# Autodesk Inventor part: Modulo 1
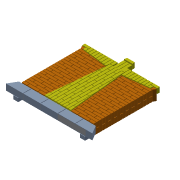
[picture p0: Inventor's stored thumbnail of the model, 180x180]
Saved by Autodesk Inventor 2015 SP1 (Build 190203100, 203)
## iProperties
Created: 2015-04
Part Number: Modulo 1
Material: Generic
Document SubType Name: Modeling
Designer: treina2
Density: 1 g/cm^3
Appearance: Default
Author: treina2
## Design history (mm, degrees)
sketch "Sketch1"
  geometry: L1 (1091.806, 200)-(1091.806, 440) reference; L2 (1091.806, 440)-(1033.806, 440) reference; L3 (1033.806, 440)-(1033.806, 200) reference; L4 (1033.806, 200)-(1091.806, 200) reference; L5 (1159.806, 200)-(1159.806, 315) reference; L6 (1159.806, 315)-(1101.806, 315) reference; L7 (1101.806, 315)-(1101.806, 200) reference; L8 (1101.806, 200)-(1159.806, 200) reference; L9 (1227.806, 200)-(1227.806, 440) reference; L10 (1227.806, 440)-(1169.806, 440) reference; L11 (1169.806, 440)-(1169.806, 200) reference; L12 (1169.806, 200)-(1227.806, 200) reference; L13 (1024, 200)-(1024, 315) reference; L14 (1024, 315)-(966, 315) reference; L15 (966, 315)-(966, 200) reference; L16 (966, 200)-(1024, 200) reference; L17 (1169.806, 1464.632)-(1169.806, 1450) reference; L18 (1169.806, 1450)-(1171.263, 1450) reference; L19 (1284.348, 315)-(1237.806, 315) reference; L20 (1237.806, 315)-(1237.806, 200) reference; L21 (1237.806, 200)-(1295.806, 200) reference; L22 (1259.439, 565)-(1283.351, 325) reference; L23 (1259.439, 565)-(1237.806, 565) reference; L24 (1237.806, 565)-(1237.806, 325) reference; L25 (1237.806, 325)-(1283.351, 325) reference; L26 (1169.806, 1565)-(1177.128, 1492) reference; L27 (1237.806, 1498.938)-(1295.806, 1505.57) reference; L28 (1295.806, 1505.57)-(1295.806, 1686) reference; L29 (1295.806, 1686)-(1237.806, 1686) reference; L30 (1237.806, 1686)-(1237.806, 1498.938) reference; L31 (1159.806, 325)-(1159.806, 565) reference; L32 (1159.806, 565)-(1101.806, 565) reference; L33 (1101.806, 565)-(1101.806, 325) reference; L34 (1101.806, 325)-(1159.806, 325) reference; L35 (1703.806, 1552.224)-(1703.806, 1686) reference; L36 (1703.806, 1686)-(1645.806, 1686) reference; L37 (1645.806, 1686)-(1645.806, 1545.592) reference; L38 (1024, 325)-(1024, 565) reference; L39 (1024, 565)-(966, 565) reference; L40 (966, 565)-(966, 325) reference; L41 (966, 325)-(1024, 325) reference; L42 (1091.806, 450)-(1091.806, 690) reference; L43 (1091.806, 690)-(1033.806, 690) reference; L44 (1033.806, 690)-(1033.806, 450) reference; L45 (1033.806, 450)-(1091.806, 450) reference; L46 (1227.806, 450)-(1227.806, 690) reference; L47 (1227.806, 690)-(1169.806, 690) reference; L48 (1169.806, 690)-(1169.806, 450) reference; L49 (1169.806, 450)-(1227.806, 450) reference; L50 (1159.806, 575)-(1159.806, 815) reference; L51 (1159.806, 815)-(1101.806, 815) reference; L52 (1101.806, 815)-(1101.806, 575) reference; L53 (1101.806, 575)-(1159.806, 575) reference; L54 (1237.806, 782.132)-(1237.806, 575) reference; L55 (1237.806, 575)-(1258.443, 575) reference; L56 (1024, 575)-(1024, 815) reference; L57 (1024, 815)-(966, 815) reference; L58 (966, 815)-(966, 575) reference; L59 (966, 575)-(1024, 575) reference; L60 (1091.806, 700)-(1091.806, 940) reference; L61 (1091.806, 940)-(1033.806, 940) reference; L62 (1033.806, 940)-(1033.806, 700) reference; L63 (1033.806, 700)-(1091.806, 700) reference; L64 (1227.806, 700)-(1227.806, 882.5) reference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; 1 further point
  constraints: 1754 end point, 397 horizontal, 367 vertical, 18 point on line, 953 other
workplane "Work Plane1"
sketch "Sketch2"
  geometry: L1 (1990, 0)-(1600, 0) reference; L2 (1990, 0)-(1880.303, 190) reference; L3 (1765, 190)-(1880.303, 190) reference; L4 (1600, 190)-(1880.303, 190) reference; L5 (1600, 0)-(1600, 190) reference; L6 (1590, 190)-(1590, 0) reference; L7 (1200, 190)-(1590, 190) reference; L8 (1590, 0)-(1200, 0) reference; L9 (1200, 0)-(1200, 190) reference; L10 (1190, 190)-(1190, 0) reference; L11 (1190, 0)-(800, 0) reference; L12 (800, 190)-(1190, 190) reference; L13 (800, 0)-(800, 190) reference; L14 (790, 190)-(790, 0) reference; L15 (400, 190)-(790, 190) reference; L16 (790, 0)-(400, 0) reference; L17 (400, 0)-(400, 190) reference; L18 (390, 190)-(390, 0) reference; L19 (109.697, 190)-(390, 190) reference; L20 (390, 0)-(0, 0) reference; L21 (0, 0)-(109.697, 190) reference; 1 further point
extrude "Extrusion1" new body sketch "Sketch2" distance "d2" = 140 (= BLOCO_PADRAO_LARG); taper "d3" = 0 deg
extrude "Extrusion2" new body sketch "Sketch2" distance "d4" = 140 (= BLOCO_PADRAO_LARG); taper "d5" = 0 deg
extrude "Extrusion3" new body sketch "Sketch2" distance "d6" = 140 (= BLOCO_PADRAO_LARG); taper "d7" = 0 deg
extrude "Extrusion4" new body sketch "Sketch2" distance "d8" = 140 (= BLOCO_PADRAO_LARG); taper "d9" = 0 deg
extrude "Extrusion5" new body sketch "Sketch2" distance "d10" = 140 (= BLOCO_PADRAO_LARG); taper "d11" = 0 deg
extrude "Extrusion6" new body sketch "Sketch1" distance "d12" = 240 (= TIJOLO_PADRAO_COMP); taper "d13" = 0 deg
extrude "Extrusion7" new body sketch "Sketch1" distance "d14" = 240 (= TIJOLO_PADRAO_COMP); taper "d15" = 0 deg
extrude "Extrusion8" new body sketch "Sketch1" distance "d16" = 115 (= TIJOLO_PADRAO_LARG); taper "d17" = 0 deg
extrude "Extrusion9" new body sketch "Sketch1" distance "d18" = 115 (= TIJOLO_PADRAO_LARG); taper "d19" = 0 deg
extrude "Extrusion10" new body sketch "Sketch1" distance "d20" = 115 (= TIJOLO_PADRAO_LARG); taper "d21" = 0 deg
extrude "Extrusion11" new body sketch "Sketch1" distance "d22" = 115 (= TIJOLO_PADRAO_LARG); taper "d23" = 0 deg
extrude "Extrusion12" new body sketch "Sketch1" distance "d24" = 115 (= TIJOLO_PADRAO_LARG); taper "d25" = 0 deg
extrude "Extrusion13" new body sketch "Sketch1" distance "d26" = 240 (= TIJOLO_PADRAO_COMP); taper "d27" = 0 deg
extrude "Extrusion14" new body sketch "Sketch1" distance "d28" = 115 (= TIJOLO_PADRAO_LARG); taper "d29" = 0 deg
extrude "Extrusion15" new body sketch "Sketch1" distance "d30" = 115 (= TIJOLO_PADRAO_LARG); taper "d31" = 0 deg
extrude "Extrusion16" new body sketch "Sketch1" distance "d32" = 115 (= TIJOLO_PADRAO_LARG); taper "d33" = 0 deg
extrude "Extrusion17" new body sketch "Sketch1" distance "d34" = 115 (= TIJOLO_PADRAO_LARG); taper "d35" = 0 deg
extrude "Extrusion18" new body sketch "Sketch1" distance "d36" = 115 (= TIJOLO_PADRAO_LARG); taper "d37" = 0 deg
extrude "Extrusion19" new body sketch "Sketch1" distance "d38" = 115 (= TIJOLO_PADRAO_LARG); taper "d39" = 0 deg
extrude "Extrusion20" new body sketch "Sketch1" distance "d40" = 115 (= TIJOLO_PADRAO_LARG); taper "d41" = 0 deg
extrude "Extrusion21" new body sketch "Sketch1" distance "d42" = 115 (= TIJOLO_PADRAO_LARG); taper "d43" = 0 deg
extrude "Extrusion22" new body sketch "Sketch1" distance "d44" = 115 (= TIJOLO_PADRAO_LARG); taper "d45" = 0 deg
extrude "Extrusion23" new body sketch "Sketch1" distance "d46" = 115 (= TIJOLO_PADRAO_LARG); taper "d47" = 0 deg
extrude "Extrusion24" new body sketch "Sketch1" distance "d48" = 240 (= TIJOLO_PADRAO_COMP); taper "d49" = 0 deg
extrude "Extrusion25" new body sketch "Sketch1" distance "d50" = 115 (= TIJOLO_PADRAO_LARG); taper "d51" = 0 deg
extrude "Extrusion26" new body sketch "Sketch1" distance "d52" = 115 (= TIJOLO_PADRAO_LARG); taper "d53" = 0 deg
extrude "Extrusion27" new body sketch "Sketch1" distance "d54" = 240 (= TIJOLO_PADRAO_COMP); taper "d55" = 0 deg
extrude "Extrusion28" new body sketch "Sketch1" distance "d56" = 115 (= TIJOLO_PADRAO_LARG); taper "d57" = 0 deg
extrude "Extrusion29" new body sketch "Sketch1" distance "d58" = 115 (= TIJOLO_PADRAO_LARG); taper "d59" = 0 deg
extrude "Extrusion30" new body sketch "Sketch1" distance "d60" = 115 (= TIJOLO_PADRAO_LARG); taper "d61" = 0 deg
extrude "Extrusion31" new body sketch "Sketch1" distance "d62" = 115 (= TIJOLO_PADRAO_LARG); taper "d63" = 0 deg
extrude "Extrusion32" new body sketch "Sketch1" distance "d64" = 115 (= TIJOLO_PADRAO_LARG); taper "d65" = 0 deg
extrude "Extrusion33" new body sketch "Sketch1" distance "d66" = 115 (= TIJOLO_PADRAO_LARG); taper "d67" = 0 deg
extrude "Extrusion34" new body sketch "Sketch1" distance "d68" = 115 (= TIJOLO_PADRAO_LARG); taper "d69" = 0 deg
extrude "Extrusion35" new body sketch "Sketch1" distance "d70" = 115 (= TIJOLO_PADRAO_LARG); taper "d71" = 0 deg
extrude "Extrusion36" new body sketch "Sketch1" distance "d72" = 240 (= TIJOLO_PADRAO_COMP); taper "d73" = 0 deg
extrude "Extrusion37" new body sketch "Sketch1" distance "d74" = 115 (= TIJOLO_PADRAO_LARG); taper "d75" = 0 deg
extrude "Extrusion38" new body sketch "Sketch1" distance "d76" = 115 (= TIJOLO_PADRAO_LARG); taper "d77" = 0 deg
extrude "Extrusion39" new body sketch "Sketch1" distance "d78" = 115 (= TIJOLO_PADRAO_LARG); taper "d79" = 0 deg
extrude "Extrusion40" new body sketch "Sketch1" distance "d80" = 115 (= TIJOLO_PADRAO_LARG); taper "d81" = 0 deg
extrude "Extrusion41" new body sketch "Sketch1" distance "d82" = 115 (= TIJOLO_PADRAO_LARG); taper "d83" = 0 deg
extrude "Extrusion42" new body sketch "Sketch1" distance "d84" = 115 (= TIJOLO_PADRAO_LARG); taper "d85" = 0 deg
extrude "Extrusion43" new body sketch "Sketch1" distance "d86" = 115 (= TIJOLO_PADRAO_LARG); taper "d87" = 0 deg
extrude "Extrusion44" new body sketch "Sketch1" distance "d88" = 240 (= TIJOLO_PADRAO_COMP); taper "d89" = 0 deg
extrude "Extrusion45" new body sketch "Sketch1" distance "d90" = 240 (= TIJOLO_PADRAO_COMP); taper "d91" = 0 deg
extrude "Extrusion46" new body sketch "Sketch1" distance "d92" = 240 (= TIJOLO_PADRAO_COMP); taper "d93" = 0 deg
extrude "Extrusion47" new body sketch "Sketch1" distance "d94" = 240 (= TIJOLO_PADRAO_COMP); taper "d95" = 0 deg
extrude "Extrusion48" new body sketch "Sketch1" distance "d96" = 240 (= TIJOLO_PADRAO_COMP); taper "d97" = 0 deg
extrude "Extrusion49" new body sketch "Sketch1" distance "d98" = 115 (= TIJOLO_PADRAO_LARG); taper "d99" = 0 deg
extrude "Extrusion50" new body sketch "Sketch1" distance "d100" = 115 (= TIJOLO_PADRAO_LARG); taper "d101" = 0 deg
extrude "Extrusion51" new body sketch "Sketch1" distance "d102" = 115 (= TIJOLO_PADRAO_LARG); taper "d103" = 0 deg
extrude "Extrusion52" new body sketch "Sketch1" distance "d104" = 115 (= TIJOLO_PADRAO_LARG); taper "d105" = 0 deg
extrude "Extrusion53" new body sketch "Sketch1" distance "d106" = 115 (= TIJOLO_PADRAO_LARG); taper "d107" = 0 deg
extrude "Extrusion54" new body sketch "Sketch1" distance "d108" = 115 (= TIJOLO_PADRAO_LARG); taper "d109" = 0 deg
extrude "Extrusion55" new body sketch "Sketch1" distance "d110" = 115 (= TIJOLO_PADRAO_LARG); taper "d111" = 0 deg
extrude "Extrusion56" new body sketch "Sketch1" distance "d112" = 115 (= TIJOLO_PADRAO_LARG); taper "d113" = 0 deg
extrude "Extrusion57" new body sketch "Sketch1" distance "d114" = 115 (= TIJOLO_PADRAO_LARG); taper "d115" = 0 deg
extrude "Extrusion58" new body sketch "Sketch1" distance "d116" = 115 (= TIJOLO_PADRAO_LARG); taper "d117" = 0 deg
extrude "Extrusion59" new body sketch "Sketch1" distance "d118" = 115 (= TIJOLO_PADRAO_LARG); taper "d119" = 0 deg
extrude "Extrusion60" new body sketch "Sketch1" distance "d120" = 115 (= TIJOLO_PADRAO_LARG); taper "d121" = 0 deg
extrude "Extrusion61" new body sketch "Sketch1" distance "d122" = 115 (= TIJOLO_PADRAO_LARG); taper "d123" = 0 deg
extrude "Extrusion62" new body sketch "Sketch1" distance "d124" = 115 (= TIJOLO_PADRAO_LARG); taper "d125" = 0 deg
extrude "Extrusion63" new body sketch "Sketch1" distance "d126" = 115 (= TIJOLO_PADRAO_LARG); taper "d127" = 0 deg
extrude "Extrusion64" new body sketch "Sketch1" distance "d128" = 115 (= TIJOLO_PADRAO_LARG); taper "d129" = 0 deg
extrude "Extrusion65" new body sketch "Sketch1" distance "d130" = 115 (= TIJOLO_PADRAO_LARG); taper "d131" = 0 deg
extrude "Extrusion66" new body sketch "Sketch1" distance "d132" = 115 (= TIJOLO_PADRAO_LARG); taper "d133" = 0 deg
extrude "Extrusion67" new body sketch "Sketch1" distance "d134" = 115 (= TIJOLO_PADRAO_LARG); taper "d135" = 0 deg
extrude "Extrusion68" new body sketch "Sketch1" distance "d136" = 115 (= TIJOLO_PADRAO_LARG); taper "d137" = 0 deg
extrude "Extrusion69" new body sketch "Sketch1" distance "d138" = 240 (= TIJOLO_PADRAO_COMP); taper "d139" = 0 deg
extrude "Extrusion70" new body sketch "Sketch1" distance "d140" = 240 (= TIJOLO_PADRAO_COMP); taper "d141" = 0 deg
extrude "Extrusion71" new body sketch "Sketch1" distance "d142" = 240 (= TIJOLO_PADRAO_COMP); taper "d143" = 0 deg
extrude "Extrusion72" new body sketch "Sketch1" distance "d144" = 240 (= TIJOLO_PADRAO_COMP); taper "d145" = 0 deg
extrude "Extrusion73" new body sketch "Sketch1" distance "d146" = 240 (= TIJOLO_PADRAO_COMP); taper "d147" = 0 deg
extrude "Extrusion74" new body sketch "Sketch1" distance "d148" = 240 (= TIJOLO_PADRAO_COMP); taper "d149" = 0 deg
extrude "Extrusion75" new body sketch "Sketch1" distance "d150" = 240 (= TIJOLO_PADRAO_COMP); taper "d151" = 0 deg
extrude "Extrusion76" new body sketch "Sketch1" distance "d152" = 240 (= TIJOLO_PADRAO_COMP); taper "d153" = 0 deg
extrude "Extrusion77" new body sketch "Sketch1" distance "d154" = 240 (= TIJOLO_PADRAO_COMP); taper "d155" = 0 deg
extrude "Extrusion78" new body sketch "Sketch1" distance "d156" = 115 (= TIJOLO_PADRAO_LARG); taper "d157" = 0 deg
extrude "Extrusion79" new body sketch "Sketch1" distance "d158" = 115 (= TIJOLO_PADRAO_LARG); taper "d159" = 0 deg
extrude "Extrusion80" new body sketch "Sketch1" distance "d160" = 115 (= TIJOLO_PADRAO_LARG); taper "d161" = 0 deg
extrude "Extrusion81" new body sketch "Sketch1" distance "d162" = 115 (= TIJOLO_PADRAO_LARG); taper "d163" = 0 deg
extrude "Extrusion82" new body sketch "Sketch1" distance "d164" = 115 (= TIJOLO_PADRAO_LARG); taper "d165" = 0 deg
extrude "Extrusion83" new body sketch "Sketch1" distance "d166" = 115 (= TIJOLO_PADRAO_LARG); taper "d167" = 0 deg
extrude "Extrusion84" new body sketch "Sketch1" distance "d168" = 115 (= TIJOLO_PADRAO_LARG); taper "d169" = 0 deg
extrude "Extrusion85" new body sketch "Sketch1" distance "d170" = 115 (= TIJOLO_PADRAO_LARG); taper "d171" = 0 deg
extrude "Extrusion86" new body sketch "Sketch1" distance "d172" = 115 (= TIJOLO_PADRAO_LARG); taper "d173" = 0 deg
extrude "Extrusion87" new body sketch "Sketch1" distance "d174" = 115 (= TIJOLO_PADRAO_LARG); taper "d175" = 0 deg
extrude "Extrusion88" new body sketch "Sketch1" distance "d176" = 115 (= TIJOLO_PADRAO_LARG); taper "d177" = 0 deg
extrude "Extrusion89" new body sketch "Sketch1" distance "d178" = 115 (= TIJOLO_PADRAO_LARG); taper "d179" = 0 deg
extrude "Extrusion90" new body sketch "Sketch1" distance "d180" = 115 (= TIJOLO_PADRAO_LARG); taper "d181" = 0 deg
pattern_linear "Rectangular Pattern1" dims "d184" = 136 (= 2 x TIJOLO_PADRAO_PROF + 2 x GAP)
pattern_linear "Rectangular Pattern2" dims "d187" = 136 (= 2 x TIJOLO_PADRAO_PROF + 2 x GAP)
pattern_linear "Rectangular Pattern3" dims "d190" = 136 (= 2 x TIJOLO_PADRAO_PROF + 2 x GAP)
extrude "Extrusion91" new body sketch "Sketch1" distance "d191" = 115 (= TIJOLO_PADRAO_LARG); taper "d192" = 0 deg
extrude "Extrusion92" new body sketch "Sketch1" distance "d193" = 115 (= TIJOLO_PADRAO_LARG); taper "d194" = 0 deg
extrude "Extrusion93" new body sketch "Sketch1" distance "d195" = 115 (= TIJOLO_PADRAO_LARG); taper "d196" = 0 deg
extrude "Extrusion94" new body sketch "Sketch1" distance "d197" = 115 (= TIJOLO_PADRAO_LARG); taper "d198" = 0 deg
extrude "Extrusion95" new body sketch "Sketch1" distance "d199" = 115 (= TIJOLO_PADRAO_LARG); taper "d200" = 0 deg
extrude "Extrusion96" new body sketch "Sketch1" distance "d201" = 115 (= TIJOLO_PADRAO_LARG); taper "d202" = 0 deg
extrude "Extrusion97" new body sketch "Sketch1" distance "d203" = 115 (= TIJOLO_PADRAO_LARG); taper "d204" = 0 deg
extrude "Extrusion98" new body sketch "Sketch1" distance "d205" = 115 (= TIJOLO_PADRAO_LARG); taper "d206" = 0 deg
extrude "Extrusion99" new body sketch "Sketch1" distance "d207" = 115 (= TIJOLO_PADRAO_LARG); taper "d208" = 0 deg
extrude "Extrusion100" new body sketch "Sketch1" distance "d209" = 115 (= TIJOLO_PADRAO_LARG); taper "d210" = 0 deg
extrude "Extrusion101" new body sketch "Sketch1" distance "d211" = 115 (= TIJOLO_PADRAO_LARG); taper "d212" = 0 deg
extrude "Extrusion102" new body sketch "Sketch1" distance "d213" = 115 (= TIJOLO_PADRAO_LARG); taper "d214" = 0 deg
extrude "Extrusion103" new body sketch "Sketch1" distance "d215" = 115 (= TIJOLO_PADRAO_LARG); taper "d216" = 0 deg
extrude "Extrusion104" new body sketch "Sketch1" distance "d217" = 115 (= TIJOLO_PADRAO_LARG); taper "d218" = 0 deg
extrude "Extrusion105" new body sketch "Sketch1" distance "d219" = 115 (= TIJOLO_PADRAO_LARG); taper "d220" = 0 deg
extrude "Extrusion106" new body sketch "Sketch1" distance "d221" = 115 (= TIJOLO_PADRAO_LARG); taper "d222" = 0 deg
extrude "Extrusion107" new body sketch "Sketch1" distance "d223" = 115 (= TIJOLO_PADRAO_LARG); taper "d224" = 0 deg
extrude "Extrusion108" new body sketch "Sketch1" distance "d225" = 115 (= TIJOLO_PADRAO_LARG); taper "d226" = 0 deg
extrude "Extrusion109" new body sketch "Sketch1" distance "d227" = 240 (= TIJOLO_PADRAO_COMP); taper "d228" = 0 deg
extrude "Extrusion110" new body sketch "Sketch1" distance "d229" = 240 (= TIJOLO_PADRAO_COMP); taper "d230" = 0 deg
workplane "Work Plane2"
sketch "Sketch3"
  geometry: L1 (898.194, 1575)-(898.194, 1815) reference; L2 (898.194, 1815)-(956.194, 1815) reference; L3 (956.194, 1815)-(956.194, 1575) reference; L4 (956.194, 1575)-(898.194, 1575) reference; L5 (966, 1575)-(966, 1815) reference; L6 (1024, 1575)-(966, 1575) reference; L7 (1024, 1815)-(1024, 1575) reference; L8 (1033.806, 1575)-(1033.806, 1815) reference; L9 (1091.806, 1575)-(1033.806, 1575) reference; L10 (1091.806, 1815)-(1091.806, 1575) reference; L11 (1033.806, 1815)-(1091.806, 1815) reference; L12 (966, 1815)-(1024, 1815) reference; 1 further point
extrude "Extrusion111" new body sketch "Sketch3" distance "d232" = 115 (= AMAR_PADRAO_LARG); taper "d233" = 0 deg
extrude "Extrusion112" new body sketch "Sketch3" distance "d234" = 115 (= AMAR_PADRAO_LARG); taper "d235" = 0 deg
extrude "Extrusion113" new body sketch "Sketch3" distance "d236" = 115 (= AMAR_PADRAO_LARG); taper "d237" = 0 deg
workplane "Work Plane3"
sketch "Sketch4"
  geometry: L1 (1081.579, 1883)-(908.421, 1883) reference; L2 (898.194, 1825)-(908.421, 1883) reference; L3 (898.194, 1825)-(1091.806, 1825) reference; L4 (1091.806, 1825)-(1081.579, 1883) reference; 1 further point
extrude "Extrusion114" new body sketch "Sketch4" distance "d239" = 115 (= AMAR_PADRAO_LARG); taper "d240" = 0 deg
workplane "Work Plane4"
sketch "Sketch5"
  geometry: L1 (1091.806, 200)-(1091.806, 440) reference; L2 (1091.806, 440)-(1033.806, 440) reference; L3 (1033.806, 440)-(1033.806, 200) reference; L4 (1033.806, 200)-(1091.806, 200) reference; L5 (1159.806, 200)-(1159.806, 315) reference; L6 (1159.806, 315)-(1101.806, 315) reference; L7 (1101.806, 315)-(1101.806, 200) reference; L8 (1101.806, 200)-(1159.806, 200) reference; L9 (1227.806, 200)-(1227.806, 440) reference; L10 (1227.806, 440)-(1169.806, 440) reference; L11 (1169.806, 440)-(1169.806, 200) reference; L12 (1169.806, 200)-(1227.806, 200) reference; L13 (1024, 200)-(1024, 315) reference; L14 (1024, 315)-(966, 315) reference; L15 (966, 315)-(966, 200) reference; L16 (966, 200)-(1024, 200) reference; L17 (1169.806, 1464.632)-(1169.806, 1450) reference; L18 (1169.806, 1450)-(1171.263, 1450) reference; L19 (1284.348, 315)-(1237.806, 315) reference; L20 (1237.806, 315)-(1237.806, 200) reference; L21 (1237.806, 200)-(1295.806, 200) reference; L22 (1259.439, 565)-(1283.351, 325) reference; L23 (1259.439, 565)-(1237.806, 565) reference; L24 (1237.806, 565)-(1237.806, 325) reference; L25 (1237.806, 325)-(1283.351, 325) reference; L26 (1169.806, 1565)-(1177.128, 1492) reference; L27 (1237.806, 1498.938)-(1295.806, 1505.57) reference; L28 (1295.806, 1505.57)-(1295.806, 1686) reference; L29 (1295.806, 1686)-(1237.806, 1686) reference; L30 (1237.806, 1686)-(1237.806, 1498.938) reference; L31 (1159.806, 325)-(1159.806, 565) reference; L32 (1159.806, 565)-(1101.806, 565) reference; L33 (1101.806, 565)-(1101.806, 325) reference; L34 (1101.806, 325)-(1159.806, 325) reference; L35 (1703.806, 1552.224)-(1703.806, 1686) reference; L36 (1703.806, 1686)-(1645.806, 1686) reference; L37 (1645.806, 1686)-(1645.806, 1545.592) reference; L38 (1024, 325)-(1024, 565) reference; L39 (1024, 565)-(966, 565) reference; L40 (966, 565)-(966, 325) reference; L41 (966, 325)-(1024, 325) reference; L42 (1091.806, 450)-(1091.806, 690) reference; L43 (1091.806, 690)-(1033.806, 690) reference; L44 (1033.806, 690)-(1033.806, 450) reference; L45 (1033.806, 450)-(1091.806, 450) reference; L46 (1227.806, 450)-(1227.806, 690) reference; L47 (1227.806, 690)-(1169.806, 690) reference; L48 (1169.806, 690)-(1169.806, 450) reference; L49 (1169.806, 450)-(1227.806, 450) reference; L50 (1159.806, 575)-(1159.806, 815) reference; L51 (1159.806, 815)-(1101.806, 815) reference; L52 (1101.806, 815)-(1101.806, 575) reference; L53 (1101.806, 575)-(1159.806, 575) reference; L54 (1237.806, 782.132)-(1237.806, 575) reference; L55 (1237.806, 575)-(1258.443, 575) reference; L56 (1024, 575)-(1024, 815) reference; L57 (1024, 815)-(966, 815) reference; L58 (966, 815)-(966, 575) reference; L59 (966, 575)-(1024, 575) reference; L60 (1091.806, 700)-(1091.806, 940) reference; L61 (1091.806, 940)-(1033.806, 940) reference; L62 (1033.806, 940)-(1033.806, 700) reference; L63 (1033.806, 700)-(1091.806, 700) reference; L64 (1227.806, 700)-(1227.806, 882.5) reference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; 2 further points
  constraints: 1754 end point, 397 horizontal, 367 vertical, 18 point on line, 953 other
extrude "Extrusion115" new body sketch "Sketch5" distance "d242" = 115 (= AMAR_PADRAO_LARG); taper "d243" = 0 deg
extrude "Extrusion116" new body sketch "Sketch5" distance "d244" = 115 (= AMAR_PADRAO_LARG); taper "d245" = 0 deg
extrude "Extrusion117" new body sketch "Sketch5" distance "d246" = 115 (= AMAR_PADRAO_LARG); taper "d247" = 0 deg
extrude "Extrusion118" new body sketch "Sketch5" distance "d248" = 115 (= AMAR_PADRAO_LARG); taper "d249" = 0 deg
extrude "Extrusion119" new body sketch "Sketch5" distance "d250" = 115 (= AMAR_PADRAO_LARG); taper "d251" = 0 deg
extrude "Extrusion120" new body sketch "Sketch5" distance "d252" = 115 (= AMAR_PADRAO_LARG); taper "d253" = 0 deg
extrude "Extrusion121" new body sketch "Sketch5" distance "d254" = 115 (= AMAR_PADRAO_LARG); taper "d255" = 0 deg
extrude "Extrusion122" new body sketch "Sketch5" distance "d256" = 115 (= AMAR_PADRAO_LARG); taper "d257" = 0 deg
extrude "Extrusion123" new body sketch "Sketch5" distance "d258" = 115 (= AMAR_PADRAO_LARG); taper "d259" = 0 deg
extrude "Extrusion124" new body sketch "Sketch5" distance "d260" = 115 (= AMAR_PADRAO_LARG); taper "d261" = 0 deg
extrude "Extrusion125" new body sketch "Sketch5" distance "d262" = 115 (= AMAR_PADRAO_LARG); taper "d263" = 0 deg
extrude "Extrusion126" new body sketch "Sketch5" distance "d264" = 115 (= AMAR_PADRAO_LARG); taper "d265" = 0 deg
extrude "Extrusion127" new body sketch "Sketch5" distance "d266" = 115 (= AMAR_PADRAO_LARG); taper "d267" = 0 deg
extrude "Extrusion128" new body sketch "Sketch5" distance "d268" = 115 (= AMAR_PADRAO_LARG); taper "d269" = 0 deg
extrude "Extrusion129" new body sketch "Sketch5" distance "d270" = 115 (= AMAR_PADRAO_LARG); taper "d271" = 0 deg
extrude "Extrusion130" new body sketch "Sketch5" distance "d272" = 115 (= AMAR_PADRAO_LARG); taper "d273" = 0 deg
extrude "Extrusion131" new body sketch "Sketch5" distance "d274" = 115 (= AMAR_PADRAO_LARG); taper "d275" = 0 deg
extrude "Extrusion132" new body sketch "Sketch5" distance "d276" = 115 (= AMAR_PADRAO_LARG); taper "d277" = 0 deg
extrude "Extrusion133" new body sketch "Sketch5" distance "d278" = 115 (= AMAR_PADRAO_LARG); taper "d279" = 0 deg
extrude "Extrusion134" new body sketch "Sketch5" distance "d280" = 115 (= AMAR_PADRAO_LARG); taper "d281" = 0 deg
extrude "Extrusion135" new body sketch "Sketch5" distance "d282" = 115 (= AMAR_PADRAO_LARG); taper "d283" = 0 deg
extrude "Extrusion136" new body sketch "Sketch5" distance "d284" = 115 (= AMAR_PADRAO_LARG); taper "d285" = 0 deg
extrude "Extrusion137" new body sketch "Sketch5" distance "d286" = 115 (= AMAR_PADRAO_LARG); taper "d287" = 0 deg
extrude "Extrusion138" new body sketch "Sketch5" distance "d288" = 115 (= AMAR_PADRAO_LARG); taper "d289" = 0 deg
extrude "Extrusion139" new body sketch "Sketch5" distance "d290" = 115 (= AMAR_PADRAO_LARG); taper "d291" = 0 deg
extrude "Extrusion140" new body sketch "Sketch5" distance "d292" = 115 (= AMAR_PADRAO_LARG); taper "d293" = 0 deg
extrude "Extrusion141" new body sketch "Sketch5" distance "d294" = 115 (= AMAR_PADRAO_LARG); taper "d295" = 0 deg
extrude "Extrusion142" new body sketch "Sketch5" distance "d296" = 115 (= AMAR_PADRAO_LARG); taper "d297" = 0 deg
extrude "Extrusion143" new body sketch "Sketch5" distance "d298" = 115 (= AMAR_PADRAO_LARG); taper "d299" = 0 deg
extrude "Extrusion144" new body sketch "Sketch5" distance "d300" = 115 (= AMAR_PADRAO_LARG); taper "d301" = 0 deg
extrude "Extrusion145" new body sketch "Sketch5" distance "d302" = 115 (= AMAR_PADRAO_LARG); taper "d303" = 0 deg
extrude "Extrusion146" new body sketch "Sketch5" distance "d304" = 115 (= AMAR_PADRAO_LARG); taper "d305" = 0 deg
extrude "Extrusion147" new body sketch "Sketch5" distance "d306" = 115 (= AMAR_PADRAO_LARG); taper "d307" = 0 deg
extrude "Extrusion148" new body sketch "Sketch5" distance "d308" = 115 (= AMAR_PADRAO_LARG); taper "d309" = 0 deg
extrude "Extrusion149" new body sketch "Sketch5" distance "d310" = 115 (= AMAR_PADRAO_LARG); taper "d311" = 0 deg
extrude "Extrusion150" new body sketch "Sketch5" distance "d312" = 115 (= AMAR_PADRAO_LARG); taper "d313" = 0 deg
extrude "Extrusion151" new body sketch "Sketch5" distance "d314" = 115 (= AMAR_PADRAO_LARG); taper "d315" = 0 deg
extrude "Extrusion152" new body sketch "Sketch5" distance "d316" = 115 (= AMAR_PADRAO_LARG); taper "d317" = 0 deg
extrude "Extrusion153" new body sketch "Sketch5" distance "d318" = 115 (= AMAR_PADRAO_LARG); taper "d319" = 0 deg
extrude "Extrusion154" new body sketch "Sketch5" distance "d320" = 115 (= AMAR_PADRAO_LARG); taper "d321" = 0 deg
extrude "Extrusion155" new body sketch "Sketch5" distance "d322" = 115 (= AMAR_PADRAO_LARG); taper "d323" = 0 deg
extrude "Extrusion156" new body sketch "Sketch5" distance "d324" = 115 (= AMAR_PADRAO_LARG); taper "d325" = 0 deg
extrude "Extrusion157" new body sketch "Sketch5" distance "d326" = 115 (= AMAR_PADRAO_LARG); taper "d327" = 0 deg
extrude "Extrusion158" new body sketch "Sketch5" distance "d328" = 115 (= AMAR_PADRAO_LARG); taper "d329" = 0 deg
extrude "Extrusion159" new body sketch "Sketch5" distance "d330" = 115 (= AMAR_PADRAO_LARG); taper "d331" = 0 deg
extrude "Extrusion160" new body sketch "Sketch5" distance "d332" = 115 (= AMAR_PADRAO_LARG); taper "d333" = 0 deg
extrude "Extrusion161" new body sketch "Sketch5" distance "d334" = 115 (= AMAR_PADRAO_LARG); taper "d335" = 0 deg
extrude "Extrusion162" new body sketch "Sketch5" distance "d336" = 115 (= AMAR_PADRAO_LARG); taper "d337" = 0 deg
extrude "Extrusion163" new body sketch "Sketch5" distance "d338" = 115 (= AMAR_PADRAO_LARG); taper "d339" = 0 deg
extrude "Extrusion164" new body sketch "Sketch5" distance "d340" = 115 (= AMAR_PADRAO_LARG); taper "d341" = 0 deg
extrude "Extrusion165" new body sketch "Sketch5" distance "d342" = 115 (= AMAR_PADRAO_LARG); taper "d343" = 0 deg
extrude "Extrusion166" new body sketch "Sketch5" distance "d344" = 115 (= AMAR_PADRAO_LARG); taper "d345" = 0 deg
extrude "Extrusion167" new body sketch "Sketch5" distance "d346" = 115 (= AMAR_PADRAO_LARG); taper "d347" = 0 deg
extrude "Extrusion168" new body sketch "Sketch5" distance "d348" = 115 (= AMAR_PADRAO_LARG); taper "d349" = 0 deg
extrude "Extrusion169" new body sketch "Sketch5" distance "d350" = 115 (= AMAR_PADRAO_LARG); taper "d351" = 0 deg
extrude "Extrusion170" new body sketch "Sketch5" distance "d352" = 115 (= AMAR_PADRAO_LARG); taper "d353" = 0 deg
extrude "Extrusion171" new body sketch "Sketch5" distance "d354" = 115 (= AMAR_PADRAO_LARG); taper "d355" = 0 deg
extrude "Extrusion172" new body sketch "Sketch5" distance "d356" = 115 (= AMAR_PADRAO_LARG); taper "d357" = 0 deg
extrude "Extrusion173" new body sketch "Sketch5" distance "d358" = 115 (= AMAR_PADRAO_LARG); taper "d359" = 0 deg
extrude "Extrusion174" new body sketch "Sketch5" distance "d360" = 115 (= AMAR_PADRAO_LARG); taper "d361" = 0 deg
extrude "Extrusion175" new body sketch "Sketch5" distance "d362" = 115 (= AMAR_PADRAO_LARG); taper "d363" = 0 deg
extrude "Extrusion176" new body sketch "Sketch5" distance "d364" = 115 (= AMAR_PADRAO_LARG); taper "d365" = 0 deg
extrude "Extrusion177" new body sketch "Sketch5" distance "d366" = 115 (= AMAR_PADRAO_LARG); taper "d367" = 0 deg
extrude "Extrusion178" new body sketch "Sketch5" distance "d368" = 115 (= AMAR_PADRAO_LARG); taper "d369" = 0 deg
extrude "Extrusion179" new body sketch "Sketch5" distance "d370" = 115 (= AMAR_PADRAO_LARG); taper "d371" = 0 deg
extrude "Extrusion180" new body sketch "Sketch5" distance "d372" = 115 (= AMAR_PADRAO_LARG); taper "d373" = 0 deg
extrude "Extrusion181" new body sketch "Sketch5" distance "d374" = 115 (= AMAR_PADRAO_LARG); taper "d375" = 0 deg
extrude "Extrusion182" new body sketch "Sketch5" distance "d376" = 115 (= AMAR_PADRAO_LARG); taper "d377" = 0 deg
workplane "Work Plane5"
sketch "Sketch6"
  geometry: L1 (-167.194, 1492)-(-282.194, 1492); L2 (-282.194, 1492)-(-282.194, 1550); L3 (-282.194, 1550)-(-167.194, 1550); L4 (-167.194, 1550)-(-167.194, 1492); 1 further point
  constraints: 8 end point, 2 parallel, 1 horizontal, 1 perpendicular
  dimensions: "d379" = 58 distance of L3.end L1.start (= TIJOLO_PADRAO_PROF); "d380" = 115 distance of L1.start L1.end (= TIJOLO_PADRAO_LARG)
extrude "Extrusion183" new body sketch "Sketch6" distance "d381" = 115 (= AMAR_PADRAO_LARG); taper "d382" = 0 deg
pattern_linear "Rectangular Pattern4" dims "d385" = 136 (= 2 x TIJOLO_PADRAO_PROF + 2 x GAP)
sketch "Sketch7"
  geometry: L1 (-1822.806, 1492)-(-1707.806, 1492); L2 (-1707.806, 1492)-(-1707.806, 1550); L3 (-1707.806, 1550)-(-1822.806, 1550); L4 (-1822.806, 1550)-(-1822.806, 1492); 1 further point
  constraints: 8 end point, 2 parallel, 1 horizontal, 1 perpendicular
  dimensions: "d386" = 115 distance of L2.end L3.end (= TIJOLO_PADRAO_LARG); "d387" = 58 distance of L3.end L1.start (= TIJOLO_PADRAO_PROF)
extrude "Extrusion184" new body sketch "Sketch7" distance "d388" = 115 (= AMAR_PADRAO_LARG); taper "d389" = 0 deg
pattern_linear "Rectangular Pattern5" dims "d392" = 136 (= 2 x TIJOLO_PADRAO_PROF + 2 x GAP)
workplane "Work Plane6"
sketch "Sketch8"
  geometry: L1 (0, 0)-(0, -240) reference; L2 (115, -240)-(0, -240); L3 (0, -240)-(0, -160); L4 (0, -160)-(115, -160); L5 (115, -160)-(115, -240); L6 (222.806, -150)-(-167.194, -150) reference; 1 further point
  constraints: 8 end point, 2 parallel, 1 horizontal, 1 perpendicular, 1 point on line
  dimensions: "d394" = 10 distance between parallel lines of L6 L4
extrude "Extrusion185" new body sketch "Sketch8" stored distance "d395" = 115 (= AMAR_PADRAO_LARG); taper "d396" = 0 deg
sketch "Sketch9"
  geometry: L1 (1540.611, 0)-(1540.611, -240) reference; L2 (1655.611, -240)-(1540.611, -240); L3 (1540.611, -240)-(1540.611, -160); L4 (1540.611, -160)-(1655.611, -160); L5 (1655.611, -160)-(1655.611, -240); L6 (1822.806, -150)-(1432.806, -150) reference; 1 further point
  constraints: 8 end point, 2 parallel, 1 horizontal, 1 perpendicular, 1 point on line
  dimensions: "d397" = 10 distance between parallel lines of L6 L4
extrude "Extrusion186" new body sketch "Sketch9" stored distance "d398" = 115 (= AMAR_PADRAO_LARG); taper "d399" = 0 deg
sketch "Sketch10"
  geometry: L1 (-10, 0)-(-400, 0) reference; L2 (-10, -140)-(-400, -140) reference; L3 (-1050, -10)-(640, -10); L4 (640, -10)-(640, -130); L5 (640, -130)-(-1050, -130); L6 (-1050, -130)-(-1050, -10); L7 (-1200, 0)-(-1200, -140) reference; L8 (790, 0)-(790, -140) reference; 1 further point
  constraints: 8 end point, 2 parallel, 1 horizontal, 1 perpendicular
  dimensions: "d400" = 10 distance between parallel lines of L1 L3; "d401" = 10 distance between parallel lines of L5 L2 (= d400); "d402" = 150 distance between parallel lines of L8 L4; "d403" = 150 distance between parallel lines of L7 L6 (= d402)
extrude "Extrusion187" new body sketch "Sketch10" distance "d404" = 190; taper "d405" = 0 deg
sketch "Sketch11"
  geometry: L1 (105.855, -10)-(247.806, -10) reference; L2 (-108.194, 95)-(-166.194, 95) reference; L3 (612.806, 10)-(-1022.806, 10); L4 (-1022.806, 10)-(-1022.806, 85); L5 (-1022.806, 85)-(612.806, 85); L6 (612.806, 85)-(612.806, 10); L7 (390, 0)-(0, 0) reference; L8 (622.806, -10)-(622.806, 230) reference; L9 (-1032.806, -10)-(-1032.806, 230) reference; 1 further point
  constraints: 8 end point, 2 parallel, 1 horizontal, 1 perpendicular
  dimensions: "d406" = 10 distance between parallel lines of L7 L3; "d407" = 10 distance between parallel lines of L2 L5 (= d406); "d408" = 10 distance between parallel lines of L9 L4 (= d406); "d409" = 10 distance between parallel lines of L8 L6 (= d406)
extrude "Extrusion188" join sketch "Sketch11" distance "d410" = 1481; taper "d411" = 0 deg
sketch "Sketch12"
  geometry: L1 (-108.194, -5)-(-108.194, 110) reference; L2 (-301.806, -5)-(-301.806, 110) reference; L3 (612.806, 85)-(-1022.806, 85) reference; L4 (-1022.806, 10)-(612.806, 10) reference; L5 (-1050, 10)-(640, 10) reference; L6 (-118.194, 10)-(-291.806, 10); L7 (-291.806, 10)-(-291.806, 85); L8 (-291.806, 85)-(-118.194, 85); L9 (-118.194, 85)-(-118.194, 10); 1 further point
  constraints: 8 end point, 2 parallel, 2 point on line, 1 horizontal, 1 perpendicular
  dimensions: "d412" = 10 distance between parallel lines of L7 L2; "d413" = 10 distance between parallel lines of L1 L9 (= d412)
extrude "Extrusion189" join sketch "Sketch12" distance "d414" = 155; taper "d415" = 0 deg
sketch "Sketch13"
  geometry: L1 (105, 1360)-(-10, 1360) reference; L2 (105, 1302)-(105, 1360) reference; L3 (-10, 1360)-(-10, 1302) reference; L4 (1645.611, 1360)-(1530.611, 1360) reference; L5 (1645.611, 1302)-(1645.611, 1360) reference; L6 (1530.611, 1360)-(1530.611, 1302) reference; L7 (0, 0)-(0, 1481) reference; L8 (1635.611, 0)-(1635.611, 1481) reference; L9 (0, 0)-(95, 0); L10 (95, 0)-(95, 1360); L11 (95, 1360)-(0, 1360); L12 (0, 1360)-(0, 0); L13 (1635.611, 0)-(1540.611, 0); L14 (1540.611, 0)-(1540.611, 1360); L15 (1540.611, 1360)-(1635.611, 1360); L16 (1635.611, 1360)-(1635.611, 0); 1 further point
  constraints: 16 end point, 4 parallel, 2 horizontal, 2 perpendicular, 2 point on line
  dimensions: "d416" = 10 distance between parallel lines of L14 L6; "d417" = 10 distance between parallel lines of L2 L10 (= d416)
extrude "Extrusion190" join sketch "Sketch13" distance "d418" = 140; taper "d419" = 0 deg
node "M1.1"
node "M1.6"
node "M1.5"
node "M1.2"
node "M1.3"
node "M1.4"
node "M1.7"
node "M1.8"
node "M1.9"
node "M1.10"
node "M1.11"
node "M1.12"
node "M1.13"
node "M1.14"
node "M1.15"
node "M1.16"
node "M1.17"
node "M1.18"
node "M1.19"
node "M1.20"
node "M1.21"
node "M1.22"
node "M1.23"
node "M1.24"
node "M1.25"
node "M1.26"
node "M1.27"
node "M1.28"
node "M1.29"
node "M1.30"
node "M1.31"
node "M1.32"
node "M1.33"
node "M1.34"
node "M1.35"
node "M1.36"
node "M1.37"
node "M1.38"
node "M1.39"
node "M1.40"
node "M1.41"
node "M1.42"
node "M1.43"
node "M1.44"
node "M1.45"
node "M1.46"
node "M1.47"
node "M1.48"
node "M1.49"
node "M1.50"
node "M1.51"
node "M1.52"
node "M1.53"
node "M1.54"
node "M1.55"
node "M1.56"
node "M1.57"
node "M1.58"
node "M1.59"
node "M1.60"
node "M1.61"
node "M1.62"
node "M1.63"
node "M1.64"
node "M1.65"
node "M1.66"
node "M1.67"
node "M1.68"
node "M1.69"
node "M1.70"
node "M1.71"
node "M1.72"
node "M1.73"
node "M1.74"
node "M1.75"
node "M1.76"
node "M1.77"
node "M1.78"
node "M1.79"
node "M1.80"
node "M1.81"
node "M1.82"
node "M1.83"
node "M1.84"
node "M1.85"
node "M1.86"
node "M1.87"
node "M1.88"
node "M1.89"
node "M1.90"
feature "Pattern of M1.90:1"
node "M1.91"
feature "Pattern of M1.90:2"
node "M1.92"
feature "Pattern of M1.90:3"
node "M1.93"
feature "Pattern of M1.90:4"
node "M1.94"
feature "Pattern of M1.90:5"
node "M1.95"
feature "Pattern of M1.90:6"
node "M1.96"
feature "Pattern of M1.90:7"
node "M1.97"
feature "Pattern of M1.90:8"
node "M1.98"
feature "Pattern of M1.90:9"
node "M1.99"
feature "Pattern of M1.90:10"
node "M1.100"
feature "Pattern of M1.90:11"
node "M1.101"
feature "Pattern of M1.90:12"
node "M1.102"
feature "Pattern of M1.90:13"
node "M1.103"
feature "Pattern of M1.90:14"
node "M1.104"
feature "Pattern of M1.90:15"
node "M1.105"
feature "Pattern of M1.90:16"
node "M1.106"
feature "Pattern of M1.90:17"
node "M1.107"
feature "Pattern of M1.90:18"
node "M1.108"
feature "Pattern of M1.90:19"
node "M1.109"
feature "Pattern of M1.90:20"
node "M1.110"
feature "Pattern of M1.90:21"
node "M1.111"
node "M1.112"
node "M1.113"
node "M1.114"
node "M1.115"
node "M1.116"
node "M1.117"
node "M1.118"
node "M1.119"
node "M1.120"
node "M1.121"
node "M1.122"
node "M1.123"
node "M1.124"
node "M1.125"
node "M1.126"
node "M1.127"
node "M1.128"
node "M1.129"
node "M1.130"
node "M1.131"
node "M1.132"
node "M1.133"
node "M1.134"
node "M1.135"
node "M1.136"
node "M1.137"
node "M1.138"
node "M1.139"
node "M1.140"
node "M1.141"
node "M1.142"
node "M1.143"
node "M1.144"
node "M1.145"
node "M1.146"
node "M1.147"
node "M1.148"
node "M1.149"
node "M1.150"
node "M1.151"
node "M1.152"
node "M1.153"
node "M1.154"
node "M1.155"
node "M1.156"
node "M1.157"
node "M1.158"
node "M1.159"
node "M1.160"
node "M1.161"
node "M1.162"
node "M1.163"
node "M1.164"
node "M1.165"
node "M1.166"
node "M1.167"
node "M1.168"
node "M1.169"
node "M1.170"
node "M1.171"
node "M1.172"
node "M1.173"
node "M1.174"
node "M1.175"
node "M1.176"
node "M1.177"
node "M1.178"
node "M1.179"
node "M1.180"
node "M1.181"
node "M1.182"
node "M1.183"
node "M1.184"
node "M1.185"
node "M1.186"
node "M1.187"
node "M1.188"
node "M1.189"
node "M1.190"
node "M1.191"
node "M1.192"
node "M1.193"
node "M1.194"
node "M1.195"
node "M1.196"
node "M1.197"
node "M1.198"
node "M1.199"
node "M1.200"
node "M1.201"
node "M1.202"
node "M1.203"
node "M1.204"
feature "Pattern of M1.204:22"
node "M1.205"
feature "Pattern of M1.204:23"
node "M1.206"
feature "Pattern of M1.204:24"
node "M1.207"
feature "Pattern of M1.204:25"
node "M1.208"
feature "Pattern of M1.204:26"
node "M1.209"
feature "Pattern of M1.204:27"
node "M1.210"
feature "Pattern of M1.204:28"
node "M1.211"
feature "Pattern of M1.204:29"
node "M1.212"
feature "Pattern of M1.204:30"
node "M1.213"
node "M1.214"
feature "Pattern of M1.214:31"
node "M1.215"
feature "Pattern of M1.214:32"
node "M1.216"
feature "Pattern of M1.214:33"
node "M1.217"
feature "Pattern of M1.214:34"
node "M1.218"
feature "Pattern of M1.214:35"
node "M1.219"
feature "Pattern of M1.214:36"
node "M1.220"
feature "Pattern of M1.214:37"
node "M1.221"
feature "Pattern of M1.214:38"
node "M1.222"
feature "Pattern of M1.214:39"
node "M1.223"
node "M1.224"
node "M1.225"
body "Solid226"
other parameters: "TIJOLO_PADRAO_COMP" = 240 [user parameter; used in 22 equation terms], "TIJOLO_PADRAO_LARG" = 115 [user parameter; used in 85 equation terms], "TIJOLO_PADRAO_PROF" = 58 [user parameter; used in 7 equation terms], "BLOCO_PADRAO_LARG" = 140 [user parameter; used in 5 equation terms], "AMAR_PADRAO_LARG" = 115 [user parameter; used in 76 equation terms], "AMAR_PADRAO_PROF" = 58 [user parameter], "d231" = -5, "d238" = 15
